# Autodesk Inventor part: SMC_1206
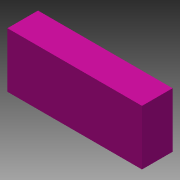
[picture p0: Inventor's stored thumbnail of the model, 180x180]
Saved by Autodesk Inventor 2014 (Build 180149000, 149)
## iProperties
Shininess: 64.0
Length Units: 11272
Angle Units: 11279
Time Units: 11290
Mass Units: 11286
Length Display Precision: 3
Angle Display Precision: 2
Compacted: True
Part Number: SMC_1206
Document SubType Name: Modeling
Created: 2003-04
Designer: t_enrig
Manufacturer: Standard
Standards Organization: Custom
Density: 1 g/cm^3
Mass: 0.0162232 g
Surface Area: 0.455483 cm^2
Volume: 0.0162232 cm^3
Material: Generic
Appearance: TranslatedColorStyle
Density: 0.0
Volumn: 0.0
Area: 0.0
PropertySet Name: Model Information
Control State: 0
Master: False
Checked Out: False
Author: t_enrig
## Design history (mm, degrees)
feature "Base1"
body "Solid1"
